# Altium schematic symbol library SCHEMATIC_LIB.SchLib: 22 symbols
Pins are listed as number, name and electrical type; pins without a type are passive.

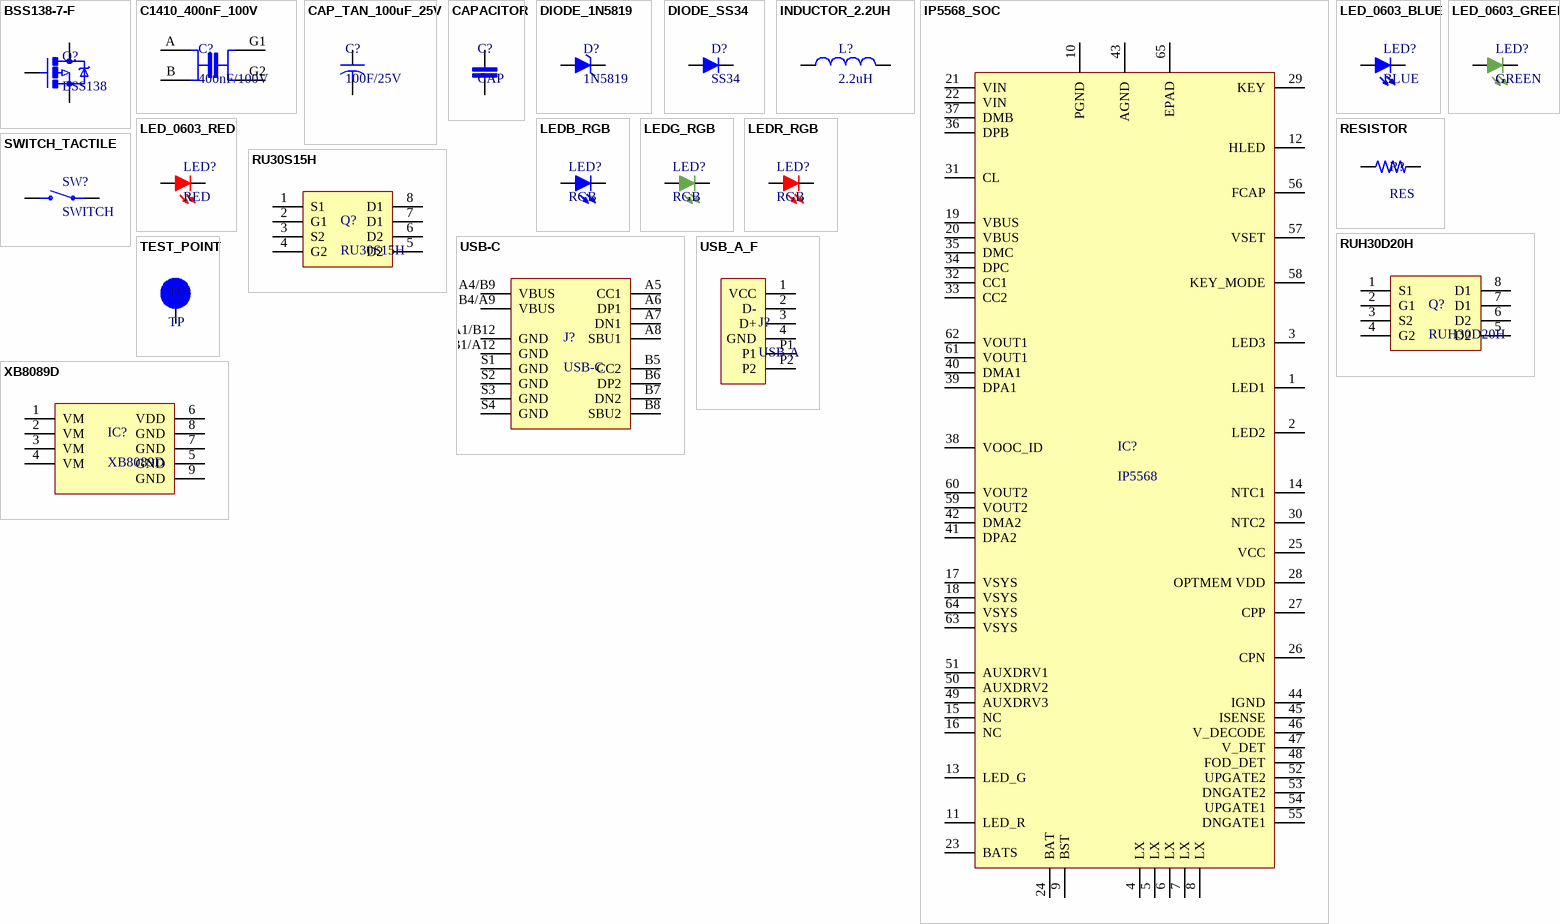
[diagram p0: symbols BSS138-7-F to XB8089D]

## BSS138-7-F
designator Q?, comment BSS138
N-Channel 50V 200mA (Ta) 300mW (Ta) Surface Mount SOT-23-3; Manufacturer: Diodes; Manufacturer Part Number: BSS138-7-F; Nominal Vgs: 1.2V; Gate to Source Voltage (Vgs): 20V; Rds On Max: 3.5R; Input Capacitance: 50pF; Number of Elements: 1; Turn-Off Delay Time: 20ns; Element Configuration: Single; Fall Time: 25ns; Rise Time: 10ns
footprint SOT23-3 (SOT23, 3-Leads, Body 2.90x2.45mm, Pitch 0.95mm, IPC Medium Density)
pins: 1 G, 2 S, 3 D

## C1410_400nF_100V
designator C?, comment 400nF/100V
400nF ±20% 100V Ceramic Capacitor X7R 1410 (3524 Metric); Manufacturer: Johanson; Manufacturer Part Number: 101X44W404MV4E
footprint C1410
pins: A, B, G1, G2

## CAP_TAN_100uF_25V
designator C?, comment 100F/25V
KEMET Tantalum Capacitor  100µF/25V Case-D (7343 Metric) 300mOhm; Manufacturer Part Number: T491X107K025AT; Capacitance: 100uF; Tolerance: 10%; ESR (Equivalent Series Resistance): 300mR; Voltage Rating: 25V; Life (Hours): 2000Hour; Leakage Current: 25uA; Polarity: Polar; Dissipation Factor: 8%; Ripple Current: 742mA
footprint CAP_TAND_7343 (7343 Metric, 7.30mm x 4.30mm)
pins: 1, 2

## CAPACITOR
designator C?, comment CAP
Chip Ceramic SMD Capacitor
footprint C0603 (Chip Capacitor, 2-Leads, Body 1.60x0.80mm, IPC Medium Density)
footprint C0805 (Chip Capacitor, 2-Leads, Body 2.00x1.25mm, IPC Medium Density)
footprint C1206
pins: 1, 2

## DIODE_1N5819
designator D?, comment 1N5819
Diode Schottky 40V 1A Surface Mount SOD-123; Manufacturer: Diodes; Manufacturer Part Number: 1N5819HW-7-F; Forward Voltage: 450mV; Peak Reverse Current: 50uA; Element Configuration: Single; Max Forward Surge Current (Ifsm): 25A; Max Power Dissipation: 450mW; Polarity: Standard; Capacitance: 110pF
footprint SOD-123
pins: A, K

## DIODE_SS34
designator D?, comment SS34
Diode Schottky 40V 3A Surface Mount SMC (DO-214AB)
footprint DIODE_ DO-214AC(SMA)
footprint DIODE_ DO-214AB(SMC)
pins: A, K

## INDUCTOR_2.2UH
designator L?, comment 2.2uH
2.2uH ±20% SMD,10x10x4mm Inductors (SMD) RoHS
footprint INDUCTOR_10X10X4
pins: 1, 2

## IP5568_SOC
designator IC?, comment IP5568
Bi-directional PD3.0 and Fast Charge protocol Power Bank & Wireless Charger SOC
footprint QFN64 (QFN, 64-Leads, Body 8.00x8.00mm, Pitch 0.40mm, Thermal Pad 6.20x6.20mm, IPC Low Density)
pins: 1 LED1, 2 LED2, 3 LED3, 4 LX, 5 LX, 6 LX, 7 LX, 8 LX, 9 BST, 10 PGND, 11 LED_R, 12 HLED, 13 LED_G, 14 NTC1, 15 NC, 16 NC, 17 VSYS, 18 VSYS, 19 VBUS, 20 VBUS, 21 VIN, 22 VIN, 23 BATS, 24 BAT, 25 VCC, 26 CPN, 27 CPP, 28 OPTMEM VDD, 29 KEY, 30 NTC2, 31 CL, 32 CC1, 33 CC2, 34 DPC, 35 DMC, 36 DPB, 37 DMB, 38 VOOC_ID, 39 DPA1, 40 DMA1, 41 DPA2, 42 DMA2, 43 AGND, 44 IGND, 45 ISENSE, 46 V_DECODE, 47 V_DET, 48 FOD_DET, 49 AUXDRV3, 50 AUXDRV2, 51 AUXDRV1, 52 UPGATE2, 53 DNGATE2, 54 UPGATE1, 55 DNGATE1, 56 FCAP, 57 VSET, 58 KEY_MODE, 59 VOUT2, 60 VOUT2, 61 VOUT1, 62 VOUT1, 63 VSYS, 64 VSYS, 65 EPAD

## LED_0603_BLUE
designator LED?, comment BLUE
BLUE LED SMT 0603
footprint LED_0603_Blue (SMD Blue LED with Package 0603)
pins: A, K

## LED_0603_GREEN
designator LED?, comment GREEN
GREEN LED SMT 0603
footprint LED_0603_Green (SMD Green LED with Package 0603)
pins: A, K

## LED_0603_RED
designator LED?, comment RED
RED LED SMT 0603
footprint LED_0603_Red (SMD Blue LED with Package 0603)
pins: A, K

## LEDB_RGB
designator LED?, comment RGB
Red, Green, Blue (RGB) 624nm Red, 525nm Green, 470nm Blue LED Indicator - Discrete 2V Red, 3.3V Green, 3.3V Blue 4-SMD; Manufacturer: Everlight; Manufacturer Part Number: EASV3015RGBA0; Color: Blue,Green,Red; Lens Color: Colorless; Test Current: 20mA; Viewing Angle: 100°; Lens Transparency: Clear; Luminous Intensity: 50mcd
footprint LED_RGB
pins: 1, 2

## LEDG_RGB
designator LED?, comment RGB
Red, Green, Blue (RGB) 624nm Red, 525nm Green, 470nm Blue LED Indicator - Discrete 2V Red, 3.3V Green, 3.3V Blue 4-SMD; Manufacturer: Everlight; Manufacturer Part Number: EASV3015RGBA0; Color: Blue,Green,Red; Lens Color: Colorless; Test Current: 20mA; Viewing Angle: 100°; Lens Transparency: Clear; Luminous Intensity: 50mcd
footprint LED_RGB
pins: 1, 3

## LEDR_RGB
designator LED?, comment RGB
Red, Green, Blue (RGB) 624nm Red, 525nm Green, 470nm Blue LED Indicator - Discrete 2V Red, 3.3V Green, 3.3V Blue 4-SMD; Manufacturer: Everlight; Manufacturer Part Number: EASV3015RGBA0; Color: Blue,Green,Red; Lens Color: Colorless; Test Current: 20mA; Viewing Angle: 100°; Lens Transparency: Clear; Luminous Intensity: 50mcd
footprint LED_RGB
pins: 1, 4

## RESISTOR
designator R?, comment RES
RESISTOR
footprint R0603 (Chip Resistor, 2-Leads, Body 1.55x0.85mm, IPC Medium Density)
footprint R1206
footprint R0805 (Chip Capacitor, 2-Leads, Body 2.00x1.25mm, IPC Medium Density)
pins: 1, 2

## RU30S15H
designator Q?
P-Channel Advanced Power MOSFET -30V/-15A
footprint SO-08
pins: 1 S1, 2 G1, 3 S2, 4 G2, 5 D2, 6 D2, 7 D1, 8 D1

## RUH30D20H
designator Q?
N-Channel Advanced Power MOSFET 30V/20A
footprint SO-08
pins: 1 S1, 2 G1, 3 S2, 4 G2, 5 D2, 6 D2, 7 D1, 8 D1

## SWITCH_TACTILE
designator SW?, comment SWITCH
Tactile Switch SPST-NO Top Actuated Surface Mount; Manufacturer: ITT C&K; Manufacturer Part Number: PTS636SM43SMTRLFS
footprint SWITCH_TACTILE
pins: 1, 2

## TEST_POINT
designator TP?, comment TP  (no BOM)
SMD Test Point
footprint TEST_POINT_3MM_ROUND
footprint TESTPOINT_1MM_ROUND
pins: 1

## USB-C
designator J?
USB-C (USB TYPE-C) USB 2.0 Receptacle Connector 24 (16+8 Dummy) Position Surface Mount, Right Angle; Through Hole; Manufacturer: Global Connector Technology; Manufacturer Part Number: USB4110-GF-A
footprint USB-C_USB4110-GF-A
pins: A1/B12 GND, A4/B9 VBUS, A5 CC1, A6 DP1, A7 DN1, A8 SBU1, B1/A12 GND, B4/A9 VBUS, B5 CC2, B6 DP2, B7 DN2, B8 SBU2, S1 GND, S2 GND, S3 GND, S4 GND

## USB_A_F
designator J?, comment USB-A
USB-A (USB TYPE-A) USB 2.0 Receptacle Connector 4 Position Through Hole, Right Angle; Manufacturer: Amphenol FCI; Manufacturer Part Number: 87520-0010BLF; Plating: Tin; Gender: Female; Connector Type: USB,Receptacle; Number of Ports: 1; Number of Contacts: 4; USB Standard: USB 2.0
footprint USB_A_F
pins: 1 VCC, 2 D-, 3 D+, 4 GND, P1, P2

## XB8089D
designator IC?
XB8089D One Cell Lithium-ion/Polymer Battery Protection IC
footprint SOP-08
pins: 1 VM, 2 VM, 3 VM, 4 VM, 5 GND, 6 VDD, 7 GND, 8 GND, 9 GND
